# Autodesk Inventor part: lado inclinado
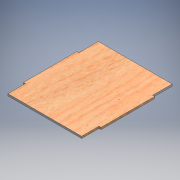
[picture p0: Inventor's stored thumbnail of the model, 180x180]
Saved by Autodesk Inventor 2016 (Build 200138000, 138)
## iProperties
Created: 2016-06
Part Number: lado inclinado
Material: Genérico
Document SubType Name: Modeling
Designer: adm
Density: 1 g/cm^3
Appearance: Valor por defecto
Author: adm
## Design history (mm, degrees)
sketch "Boceto1"
  geometry: L1 (-57, 69)-(53, 69); L2 (56, 40)-(56, -40); L3 (53, -71)-(-57, -71); L4 (-60, -40)-(-60, 40); L5 (-76.795, 75.588)-(57.893, -56.983); L6 (60, 73)-(-57, -69.35); L7 (-57, 69)-(-57, 40); L8 (-57, -40)-(-57, -71); L9 (53, 69)-(53, 40); L10 (53, -40)-(53, -71); L11 (53, -40)-(56, -40); L12 (-60, -40)-(-57, -40); L13 (-60, 40)-(-57, 40); L14 (53, 40)-(56, 40); 1 further point
  constraints: 28 end point, 3 point on line, 2 parallel, 1 horizontal, 1 perpendicular
  dimensions: "d1" = 130 distance of L6.start L5.end; "d9" = 3 distance between parallel lines of L7 L4; "d10" = 3 distance between parallel lines of L8 L4; "d11" = 3 distance between parallel lines of L10 L2; "d12" = 3 distance between parallel lines of L2 L9; "d13" = 116 distance between parallel lines of L2 L4; "d17" = 140 distance between parallel lines of L3 L1; "d18" = 31 distance between parallel lines of L3 L12
extrude "Extrusión1" new body sketch "Boceto1" distance "d7" = 3; taper "d8" = 0 deg
sketch "Boceto2"
  geometry: L1 (-57, -40)-(-57, -71) reference; L2 (53, -71)-(53, -40) reference; L3 (-57, -71)-(53, -71); L4 (53, -71)-(53, -66); L5 (53, -66)-(-57, -66); L6 (-57, -66)-(-57, -71); 1 further point
  constraints: 8 end point, 2 parallel, 1 horizontal, 1 perpendicular, 1 point on line
  dimensions: "d14" = 5 distance of L4.end L3.end
extrude "Extrusión2" cut sketch "Boceto2" distance "d15" = 10; taper "d16" = 0 deg
node "Sólido1"
other parameters: "d3" = 33, "d4" = 33, "d5" = 3, "d6" = 3
